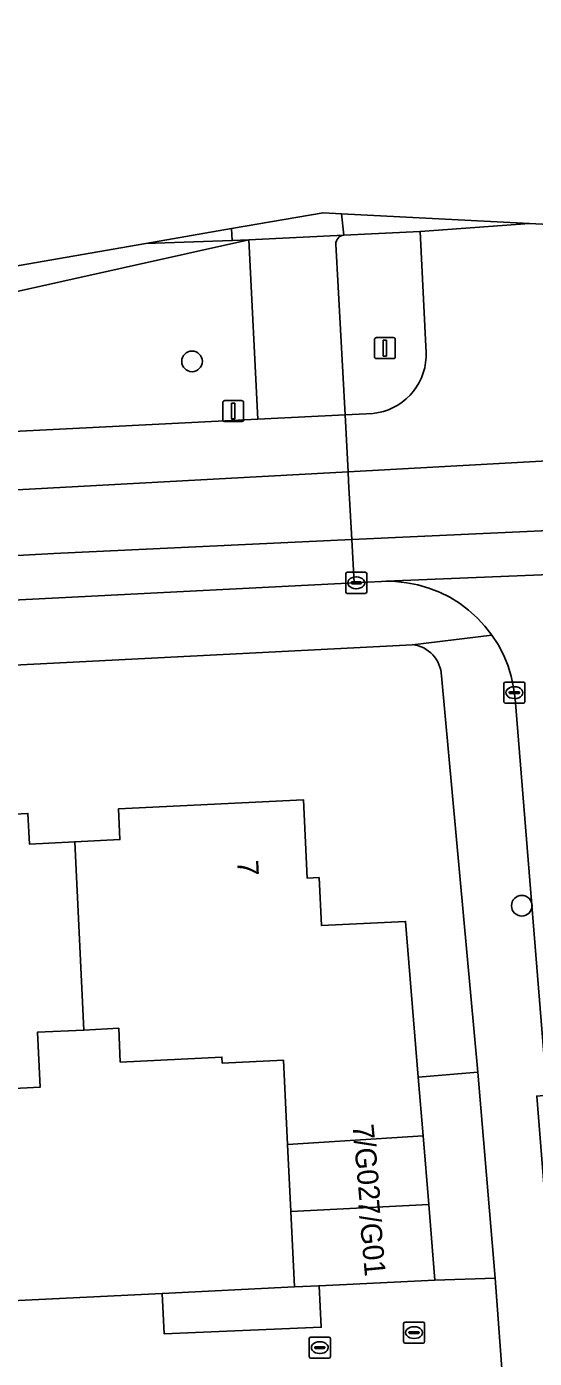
# Model space of a CAD drawing. Extents: x 161248 to 161848, y 384871 to 385383.
# Drawn here: x 161616 to 161640.1, y 385318.1 to 385381.2 of the extents above; entities that cross this region are included whole.
import ezdxf

# ---------------------------------------------------------------- set-up
doc = ezdxf.new("R2010")
doc.units = 0
for name, color, linetype in [('IMGEO_Berm_groen', 7, 'Continuous'), ('IMGEO_Boom', 7, 'Continuous'), ('IMGEO_Erf', 7, 'Continuous'), ('IMGEO_Kolk', 7, 'Continuous'), ('IMGEO_Lichtmast', 7, 'Continuous'), ('IMGEO_Pand', 7, 'Continuous'), ('IMGEO_Pand_nummerreeks', 7, 'Continuous'), ('IMGEO_Parkeervlak_open', 7, 'Continuous'), ('IMGEO_Rijbaan_lokaal_gesloten', 7, 'Continuous'), ('IMGEO_Rijbaan_lokaal_open', 7, 'Continuous'), ('IMGEO_Rijbaan_regionaal_gesloten', 7, 'Continuous'), ('IMGEO_Rioolput', 7, 'Continuous'), ('IMGEO_Verkeersbordpaal', 7, 'Continuous'), ('IMGEO_Verkeerseiland_open', 7, 'Continuous'), ('IMGEO_Voetpad_open', 7, 'Continuous')]:
    doc.layers.add(name, color=color, linetype=linetype)

msp = doc.modelspace()

# ---------------------------------------------------------------- linework, layer by layer
at = {"layer": 'IMGEO_Berm_groen'}
msp.add_lwpolyline([(161626.526, 385371.088), (161611.671, 385367.796), (161539.104, 385364.226), (161537.631, 385364.146), (161537.971, 385358.117), (161626.952, 385362.598)], close=True, dxfattribs=at)
at = {"layer": 'IMGEO_Boom'}
for centre in [(161623.826, 385365.336), (161639.463, 385339.546)]:
    msp.add_circle(centre, 0.489, dxfattribs=at)
at = {"layer": 'IMGEO_Erf'}
for points in [[(161634.282, 385351.914), (161538.595, 385347.029)], [(161575.313, 385344.386), (161577.461, 385344.491), (161577.389, 385345.958), (161586.012, 385346.379), (161594.635, 385346.799), (161594.705, 385345.368), (161596.974, 385345.479), (161597.095, 385342.995), (161607.714, 385343.512), (161616.043, 385343.918), (161616.114, 385342.47), (161618.26, 385342.575), (161620.404, 385342.68), (161620.333, 385344.136), (161629.109, 385344.564), (161629.291, 385340.849), (161629.849, 385340.876), (161629.959, 385338.607), (161633.951, 385338.802), (161634.556, 385331.43), (161637.387, 385331.666), (161635.651, 385350.437)], [(161615.263, 385320.824), (161622.411, 385321.177), (161628.68, 385321.487), (161628.506, 385325.068), (161628.351, 385328.237), (161628.157, 385332.229), (161625.258, 385332.088), (161625.244, 385332.376), (161620.424, 385332.141), (161620.347, 385333.739), (161618.696, 385333.659), (161616.491, 385333.551), (161616.617, 385330.948), (161612.881, 385330.767)]]:
    msp.add_lwpolyline(points, dxfattribs=at)
msp.add_lwpolyline([(161637.387, 385331.666), (161634.556, 385331.43), (161634.784, 385328.645), (161635.051, 385325.386), (161635.344, 385321.813), (161638.202, 385321.9)], close=True, dxfattribs=at)
msp.add_arc((161634.122, 385350.393), 1.53, 1.66114, 83.99243, dxfattribs=at)
at = {"layer": 'IMGEO_Kolk'}
for p, q in [((161631.113, 385354.419), (161631.113, 385355.271)), ((161631.188, 385355.345), (161632.04, 385355.345)), ((161631.415, 385354.888), (161631.813, 385354.888)), ((161631.601, 385355.125), (161631.626, 385355.125)), ((161632.114, 385355.271), (161632.114, 385354.419)), ((161632.04, 385354.345), (161631.188, 385354.345)), ((161631.372, 385354.839), (161631.372, 385354.851)), ((161631.81, 385354.802), (161631.412, 385354.802)), ((161631.624, 385354.565), (161631.599, 385354.565)), ((161631.856, 385354.851), (161631.856, 385354.839)), ((161638.612, 385349.216), (161638.612, 385350.068)), ((161638.687, 385350.142), (161639.539, 385350.142)), ((161639.1, 385349.922), (161639.125, 385349.922)), ((161639.613, 385350.068), (161639.613, 385349.216)), ((161638.871, 385349.636), (161638.871, 385349.648)), ((161639.309, 385349.599), (161638.911, 385349.599)), ((161638.914, 385349.685), (161639.312, 385349.685)), ((161639.123, 385349.362), (161639.098, 385349.362)), ((161639.355, 385349.648), (161639.355, 385349.636)), ((161639.539, 385349.142), (161638.687, 385349.142)), ((161629.385, 385318.187), (161629.385, 385319.039)), ((161629.46, 385319.113), (161630.312, 385319.113)), ((161630.386, 385319.039), (161630.386, 385318.187)), ((161629.644, 385318.607), (161629.644, 385318.619)), ((161630.082, 385318.57), (161629.684, 385318.57)), ((161629.687, 385318.656), (161630.085, 385318.656)), ((161629.896, 385318.333), (161629.871, 385318.333)), ((161629.873, 385318.893), (161629.898, 385318.893)), ((161630.128, 385318.619), (161630.128, 385318.607)), ((161630.312, 385318.113), (161629.46, 385318.113))]:
    msp.add_line(p, q, dxfattribs=at)
for points in [[(161631.113, 385354.419), (161631.113, 385355.271)], [(161631.188, 385355.345), (161632.04, 385355.345)], [(161632.114, 385355.271), (161632.114, 385354.419)], [(161632.04, 385354.345), (161631.188, 385354.345)], [(161638.612, 385349.216), (161638.612, 385350.068)], [(161638.687, 385350.142), (161639.539, 385350.142)], [(161639.613, 385350.068), (161639.613, 385349.216)], [(161639.539, 385349.142), (161638.687, 385349.142)], [(161629.385, 385318.187), (161629.385, 385319.039)], [(161629.46, 385319.113), (161630.312, 385319.113)], [(161630.386, 385319.039), (161630.386, 385318.187)], [(161630.312, 385318.113), (161629.46, 385318.113)]]:
    msp.add_lwpolyline(points, dxfattribs=at)
for centre, radius, start, end in [((161631.19, 385355.269), 0.0765, 91.55205, 178.44795), ((161631.19, 385355.269), 0.0765, 91.55205, 178.44795), ((161631.412, 385354.848), 0.0403, 85.87752, 175.75265), ((161631.817, 385354.85), 0.0386, 1.73085, 96.63898), ((161632.038, 385355.269), 0.0765, 1.55205, 88.44795), ((161632.038, 385355.269), 0.0765, 1.55205, 88.44795), ((161631.19, 385354.421), 0.0765, 181.55205, 268.44795), ((161631.19, 385354.421), 0.0765, 181.55205, 268.44795), ((161631.409, 385354.838), 0.0366, 178.93798, 274.71019), ((161631.813, 385354.845), 0.043, 264.86636, 352.45326), ((161632.038, 385354.421), 0.0765, 271.55205, 358.44795), ((161632.038, 385354.421), 0.0765, 271.55205, 358.44795), ((161638.689, 385350.066), 0.0765, 91.55205, 178.44795), ((161638.689, 385350.066), 0.0765, 91.55205, 178.44795), ((161639.537, 385350.066), 0.0765, 1.55205, 88.44795), ((161639.537, 385350.066), 0.0765, 1.55205, 88.44795), ((161638.689, 385349.218), 0.0765, 181.55205, 268.44795), ((161638.689, 385349.218), 0.0765, 181.55205, 268.44795), ((161638.911, 385349.645), 0.0403, 85.87752, 175.75265), ((161638.908, 385349.635), 0.0366, 178.93798, 274.71019), ((161639.312, 385349.642), 0.043, 264.86636, 352.45326), ((161639.316, 385349.647), 0.0386, 1.73085, 96.63898), ((161639.537, 385349.218), 0.0765, 271.55205, 358.44795), ((161639.537, 385349.218), 0.0765, 271.55205, 358.44795), ((161629.462, 385319.037), 0.0765, 91.55205, 178.44795), ((161629.462, 385319.037), 0.0765, 91.55205, 178.44795), ((161630.31, 385319.037), 0.0765, 1.55205, 88.44795), ((161630.31, 385319.037), 0.0765, 1.55205, 88.44795), ((161629.684, 385318.616), 0.0403, 85.87752, 175.75265), ((161629.681, 385318.606), 0.0366, 178.93798, 274.71019), ((161630.085, 385318.613), 0.043, 264.86636, 352.45326), ((161630.089, 385318.618), 0.0386, 1.73085, 96.63898), ((161629.462, 385318.189), 0.0765, 181.55205, 268.44795), ((161629.462, 385318.189), 0.0765, 181.55205, 268.44795), ((161630.31, 385318.189), 0.0765, 271.55205, 358.44795), ((161630.31, 385318.189), 0.0765, 271.55205, 358.44795)]:
    msp.add_arc(centre, radius, start, end, dxfattribs=at)
for centre, major_axis, ratio, start_param, end_param in [((161631.6, 385354.845), (-0.387, 0.002), 0.722429, 4.712389, 7.853982), ((161631.625, 385354.845), (-0.39, 0.002), 0.717154, 1.570796, 4.712389), ((161639.099, 385349.642), (-0.387, 0.002), 0.722429, 4.712389, 7.853982), ((161639.124, 385349.642), (-0.39, 0.002), 0.717154, 1.570796, 4.712389), ((161629.872, 385318.613), (-0.387, 0.002), 0.722429, 4.712389, 7.853982), ((161629.897, 385318.613), (-0.39, 0.002), 0.717154, 1.570796, 4.712389)]:
    msp.add_ellipse(centre, major_axis=major_axis, ratio=ratio, start_param=start_param, end_param=end_param, dxfattribs=at)
at = {"layer": 'IMGEO_Lichtmast'}
for p, q in [((161632.475, 385365.564), (161632.475, 385366.364)), ((161632.475, 385366.364), (161632.475, 385365.564)), ((161632.575, 385366.464), (161633.365, 385366.464)), ((161633.365, 385366.464), (161632.575, 385366.464)), ((161633.465, 385366.364), (161633.465, 385365.564)), ((161633.465, 385365.564), (161633.465, 385366.364)), ((161633.365, 385365.464), (161632.575, 385365.464)), ((161632.575, 385365.464), (161633.365, 385365.464))]:
    msp.add_line(p, q, dxfattribs=at)
msp.add_lwpolyline([(161632.895, 385366.339), (161633.045, 385366.339), (161633.045, 385365.589), (161632.895, 385365.589), (161632.895, 385366.339)], dxfattribs=at)
for centre, start, end in [((161632.575, 385366.364), 90, 180), ((161632.575, 385366.364), 90, 180), ((161633.365, 385366.364), 0, 90), ((161633.365, 385366.364), 360, 90), ((161632.575, 385365.564), 180, 270), ((161632.575, 385365.564), 180, 270), ((161633.365, 385365.564), 270, 0), ((161633.365, 385365.564), 270, 0)]:
    msp.add_arc(centre, 0.1, start, end, dxfattribs=at)
at = {"layer": 'IMGEO_Pand'}
for points in [[(161633.951, 385338.802), (161629.959, 385338.607), (161629.849, 385340.876), (161629.291, 385340.849), (161629.109, 385344.564), (161620.333, 385344.136), (161620.404, 385342.68), (161618.26, 385342.575), (161618.696, 385333.659), (161620.347, 385333.739), (161620.424, 385332.141), (161625.244, 385332.376), (161625.258, 385332.088), (161628.157, 385332.229), (161628.351, 385328.237), (161634.784, 385328.645), (161634.556, 385331.43)], [(161608.495, 385327.511), (161613.028, 385327.728), (161612.881, 385330.767), (161616.617, 385330.948), (161616.491, 385333.551), (161618.696, 385333.659), (161618.26, 385342.575), (161616.114, 385342.47), (161616.043, 385343.918), (161607.714, 385343.512)], [(161634.784, 385328.645), (161628.351, 385328.237), (161628.506, 385325.068), (161635.051, 385325.386)], [(161629.848, 385321.544), (161635.344, 385321.813), (161635.051, 385325.386), (161628.506, 385325.068), (161628.68, 385321.487)]]:
    msp.add_lwpolyline(points, close=True, dxfattribs=at)
at = {"layer": 'IMGEO_Parkeervlak_open'}
msp.add_lwpolyline([(161622.411, 385321.177), (161622.497, 385319.266), (161629.956, 385319.579), (161629.848, 385321.544), (161628.68, 385321.487)], close=True, dxfattribs=at)
at = {"layer": 'IMGEO_Rijbaan_lokaal_gesloten'}
for points in [[(161657.034, 385370.106), (161657.616, 385370.148), (161661.919, 385370.448), (161698.032, 385373.062), (161748.217, 385376.43), (161750.012, 385376.539), (161759.392, 385377.16), (161791.881, 385380.869), (161791.867, 385381.194), (161791.156, 385381.143), (161653.051, 385371.194), (161644.097, 385371.653), (161639.831, 385371.872)], [(161639.831, 385371.872), (161630.919, 385372.33), (161631.022, 385371.316), (161634.637, 385371.496), (161639.831, 385371.872)], [(161639.831, 385371.872), (161634.637, 385371.496), (161634.909, 385366.034), (161634.922, 385365.777), (161634.923, 385365.529), (161634.902, 385365.281), (161634.858, 385365.036), (161634.793, 385364.795), (161634.707, 385364.562), (161634.6, 385364.337), (161634.474, 385364.123), (161634.329, 385363.921), (161634.167, 385363.732), (161633.988, 385363.559), (161633.794, 385363.403), (161633.588, 385363.264), (161633.369, 385363.144), (161633.141, 385363.045), (161632.905, 385362.966), (161632.663, 385362.909), (161632.417, 385362.873), (161631.085, 385362.806), (161631.227, 385360.108), (161655.016, 385361.406)], [(161792.812, 385364.967), (161756.931, 385363.87), (161711.552, 385362.483), (161685.959, 385361.7), (161662.255, 385361.554), (161657.948, 385361.466), (161655.016, 385361.406), (161631.227, 385360.108), (161631.252, 385359.649), (161631.397, 385356.891), (161661.517, 385358.276), (161677.668, 385358.493), (161693.707, 385358.916), (161765.882, 385361.168), (161791.883, 385361.372)], [(161382.607, 385342.195), (161401.421, 385343.184), (161500, 385348.169), (161538.421, 385350.118), (161631.519, 385354.842), (161631.397, 385356.891), (161617.266, 385356.241), (161538.32, 385351.908), (161405.743, 385345.272), (161403.061, 385345.136), (161313.081, 385340.569), (161302.699, 385339.685), (161293.531, 385337.916), (161290.897, 385337.069), (161291.775, 385334.722), (161292.828, 385335.119)]]:
    msp.add_lwpolyline(points, dxfattribs=at)
for points in [[(161630.919, 385372.33), (161630.044, 385372.375), (161625.701, 385371.623), (161625.733, 385371.057), (161626.526, 385371.088), (161631.022, 385371.316)], [(161625.701, 385371.623), (161621.627, 385370.918), (161625.733, 385371.057)], [(161402.333, 385358.921), (161402.436, 385357.21), (161406.661, 385357.501), (161500, 385362.16), (161512.938, 385362.801), (161537.631, 385364.146), (161539.104, 385364.226), (161611.671, 385367.796), (161626.526, 385371.088), (161625.733, 385371.057), (161621.627, 385370.918), (161611.523, 385369.168), (161450.189, 385361.402)], [(161748.303, 385358.596), (161767.756, 385359.312), (161776.93, 385359.481), (161791.948, 385358.758), (161791.883, 385361.372), (161765.882, 385361.168), (161693.707, 385358.916), (161677.668, 385358.493), (161661.517, 385358.276), (161631.397, 385356.891), (161631.519, 385354.842), (161632.803, 385354.907), (161633.031, 385354.915), (161645.068, 385355.42), (161657.397, 385355.953), (161657.562, 385355.96)], [(161631.227, 385360.108), (161604.148, 385358.631), (161563.952, 385356.122), (161510.999, 385353.531), (161402.887, 385348.241), (161403.061, 385345.136), (161405.743, 385345.272), (161538.32, 385351.908), (161617.266, 385356.241), (161631.397, 385356.891), (161631.252, 385359.649)]]:
    msp.add_lwpolyline(points, close=True, dxfattribs=at)
at = {"layer": 'IMGEO_Rijbaan_lokaal_open'}
for points in [[(161645.068, 385355.42), (161633.031, 385354.915), (161633.469, 385354.905), (161634.007, 385354.85), (161634.538, 385354.746), (161635.057, 385354.595), (161635.562, 385354.399), (161636.046, 385354.158), (161636.507, 385353.875), (161636.941, 385353.552), (161637.344, 385353.192), (161637.714, 385352.797), (161638.047, 385352.37), (161638.34, 385351.916), (161638.591, 385351.437), (161638.799, 385350.937), (161638.962, 385350.421), (161639.077, 385349.893), (161639.145, 385349.356), (161640.674, 385330.569)], [(161638.643, 385315.896), (161638.202, 385321.9), (161635.344, 385321.813), (161629.848, 385321.544), (161629.956, 385319.579), (161622.497, 385319.266), (161622.411, 385321.177), (161615.263, 385320.824), (161615.349, 385318.875), (161600.471, 385318.132), (161600.41, 385320.091), (161596.55, 385319.9), (161593.478, 385319.746), (161590.407, 385319.591), (161587.335, 385319.437), (161584.263, 385319.282), (161581.191, 385319.128), (161578.119, 385318.973), (161577.87, 385323.923), (161565.206, 385323.61)]]:
    msp.add_lwpolyline(points, dxfattribs=at)
at = {"layer": 'IMGEO_Rijbaan_regionaal_gesloten'}
msp.add_lwpolyline([(161631.085, 385362.806), (161626.952, 385362.598), (161537.971, 385358.117), (161500, 385356.205), (161406.917, 385351.557), (161402.713, 385351.347), (161402.887, 385348.241), (161510.999, 385353.531), (161563.952, 385356.122), (161604.148, 385358.631), (161631.227, 385360.108)], close=True, dxfattribs=at)
at = {"layer": 'IMGEO_Rioolput'}
for p, q in [((161633.855, 385318.897), (161633.855, 385319.749)), ((161633.93, 385319.823), (161634.782, 385319.823)), ((161634.343, 385319.603), (161634.368, 385319.603)), ((161634.856, 385319.749), (161634.856, 385318.897)), ((161634.114, 385319.317), (161634.114, 385319.329)), ((161634.552, 385319.28), (161634.154, 385319.28)), ((161634.157, 385319.366), (161634.555, 385319.366)), ((161634.366, 385319.043), (161634.341, 385319.043)), ((161634.598, 385319.329), (161634.598, 385319.317)), ((161634.782, 385318.823), (161633.93, 385318.823))]:
    msp.add_line(p, q, dxfattribs=at)
for points in [[(161633.855, 385318.897), (161633.855, 385319.749)], [(161633.93, 385319.823), (161634.782, 385319.823)], [(161634.856, 385319.749), (161634.856, 385318.897)], [(161634.782, 385318.823), (161633.93, 385318.823)]]:
    msp.add_lwpolyline(points, dxfattribs=at)
for centre, radius, start, end in [((161633.932, 385319.747), 0.0765, 91.55205, 178.44795), ((161633.932, 385319.747), 0.0765, 91.55205, 178.44795), ((161634.78, 385319.747), 0.0765, 1.55205, 88.44795), ((161634.78, 385319.747), 0.0765, 1.55205, 88.44795), ((161634.154, 385319.326), 0.0403, 85.87752, 175.75265), ((161634.151, 385319.316), 0.0366, 178.93798, 274.71019), ((161634.555, 385319.323), 0.043, 264.86636, 352.45326), ((161634.559, 385319.328), 0.0386, 1.73085, 96.63898), ((161633.932, 385318.899), 0.0765, 181.55205, 268.44795), ((161633.932, 385318.899), 0.0765, 181.55205, 268.44795), ((161634.78, 385318.899), 0.0765, 271.55205, 358.44795), ((161634.78, 385318.899), 0.0765, 271.55205, 358.44795)]:
    msp.add_arc(centre, radius, start, end, dxfattribs=at)
for centre, major_axis, ratio, start_param, end_param in [((161634.342, 385319.323), (-0.387, 0.002), 0.722429, 4.712389, 7.853982), ((161634.367, 385319.323), (-0.39, 0.002), 0.717154, 1.570796, 4.712389)]:
    msp.add_ellipse(centre, major_axis=major_axis, ratio=ratio, start_param=start_param, end_param=end_param, dxfattribs=at)
at = {"layer": 'IMGEO_Verkeersbordpaal'}
for p, q in [((161625.282, 385362.581), (161625.282, 385363.381)), ((161625.282, 385363.381), (161625.282, 385362.581)), ((161625.382, 385363.481), (161626.172, 385363.481)), ((161626.172, 385363.481), (161625.382, 385363.481)), ((161626.272, 385363.381), (161626.272, 385362.581)), ((161626.272, 385362.581), (161626.272, 385363.381)), ((161626.172, 385362.481), (161625.382, 385362.481)), ((161625.382, 385362.481), (161626.172, 385362.481))]:
    msp.add_line(p, q, dxfattribs=at)
msp.add_lwpolyline([(161625.702, 385363.356), (161625.852, 385363.356), (161625.852, 385362.606), (161625.702, 385362.606), (161625.702, 385363.356)], dxfattribs=at)
for centre, start, end in [((161625.382, 385363.381), 90, 180), ((161625.382, 385363.381), 90, 180), ((161626.172, 385363.381), 0, 90), ((161626.172, 385363.381), 360, 90), ((161625.382, 385362.581), 180, 270), ((161625.382, 385362.581), 180, 270), ((161626.172, 385362.581), 270, 0), ((161626.172, 385362.581), 270, 0)]:
    msp.add_arc(centre, 0.1, start, end, dxfattribs=at)
at = {"layer": 'IMGEO_Verkeerseiland_open'}
msp.add_lwpolyline([(161630.643, 385370.895), (161631.085, 385362.806), (161632.417, 385362.873), (161632.663, 385362.909), (161632.905, 385362.966), (161633.141, 385363.045), (161633.369, 385363.144), (161633.588, 385363.264), (161633.794, 385363.403), (161633.988, 385363.559), (161634.167, 385363.732), (161634.329, 385363.921), (161634.474, 385364.123), (161634.6, 385364.337), (161634.707, 385364.562), (161634.793, 385364.795), (161634.858, 385365.036), (161634.902, 385365.281), (161634.923, 385365.529), (161634.922, 385365.777), (161634.909, 385366.034), (161634.637, 385371.496), (161631.022, 385371.316)], dxfattribs=at)
msp.add_arc((161631.069, 385370.892), 0.426, 96.3781, 179.63243, dxfattribs=at)
at = {"layer": 'IMGEO_Voetpad_open'}
for points in [[(161631.022, 385371.316), (161626.526, 385371.088), (161626.952, 385362.598), (161631.085, 385362.806), (161630.643, 385370.895)], [(161500, 385344.971), (161534.14, 385346.802), (161538.595, 385347.029), (161634.282, 385351.914), (161638.047, 385352.37), (161637.714, 385352.797), (161637.344, 385353.192), (161636.941, 385353.552), (161636.507, 385353.875), (161636.046, 385354.158), (161635.562, 385354.399), (161635.057, 385354.595), (161634.538, 385354.746), (161634.007, 385354.85), (161633.469, 385354.905), (161633.031, 385354.915), (161632.803, 385354.907), (161631.519, 385354.842), (161538.421, 385350.118), (161500, 385348.169)], [(161639.145, 385349.356), (161639.077, 385349.893), (161638.962, 385350.421), (161638.799, 385350.937), (161638.591, 385351.437), (161638.34, 385351.916), (161638.047, 385352.37), (161634.282, 385351.914)], [(161635.651, 385350.437), (161637.387, 385331.666), (161638.202, 385321.9), (161638.643, 385315.896), (161638.964, 385311.532), (161639.748, 385301.503), (161640.058, 385301.531), (161641.615, 385301.67), (161641.938, 385301.699), (161642.986, 385301.793), (161642.53, 385307.436), (161642.309, 385310.17), (161641.833, 385316.072), (161641.335, 385316.033), (161640.176, 385330.53), (161640.674, 385330.569), (161639.145, 385349.356)]]:
    msp.add_lwpolyline(points, dxfattribs=at)
for centre, radius, start, end in [((161631.069, 385370.892), 0.426, 96.3781, 179.63243), ((161634.122, 385350.393), 1.53, 1.66114, 83.99243)]:
    msp.add_arc(centre, radius, start, end, dxfattribs=at)

# ---------------------------------------------------------------- texts
at = {"layer": 'IMGEO_Pand_nummerreeks'}
for s, rotation, p in [('7', 272.80471, (161625.966, 385341.686)), ('7/G02', 275.25781, (161631.432, 385329.157)), ('7/G01', 275.31455, (161631.693, 385325.586))]:
    msp.add_text(s, height=1, rotation=rotation, dxfattribs=at).set_placement(p)

doc.saveas('drawing.dxf')
